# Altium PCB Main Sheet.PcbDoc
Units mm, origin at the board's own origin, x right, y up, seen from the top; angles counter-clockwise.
Board outline 34.5 x 33.5 mm, 2 copper layers (Top Layer, Bottom Layer); 20 components, 21 nets, 76 pads, 59 vias.
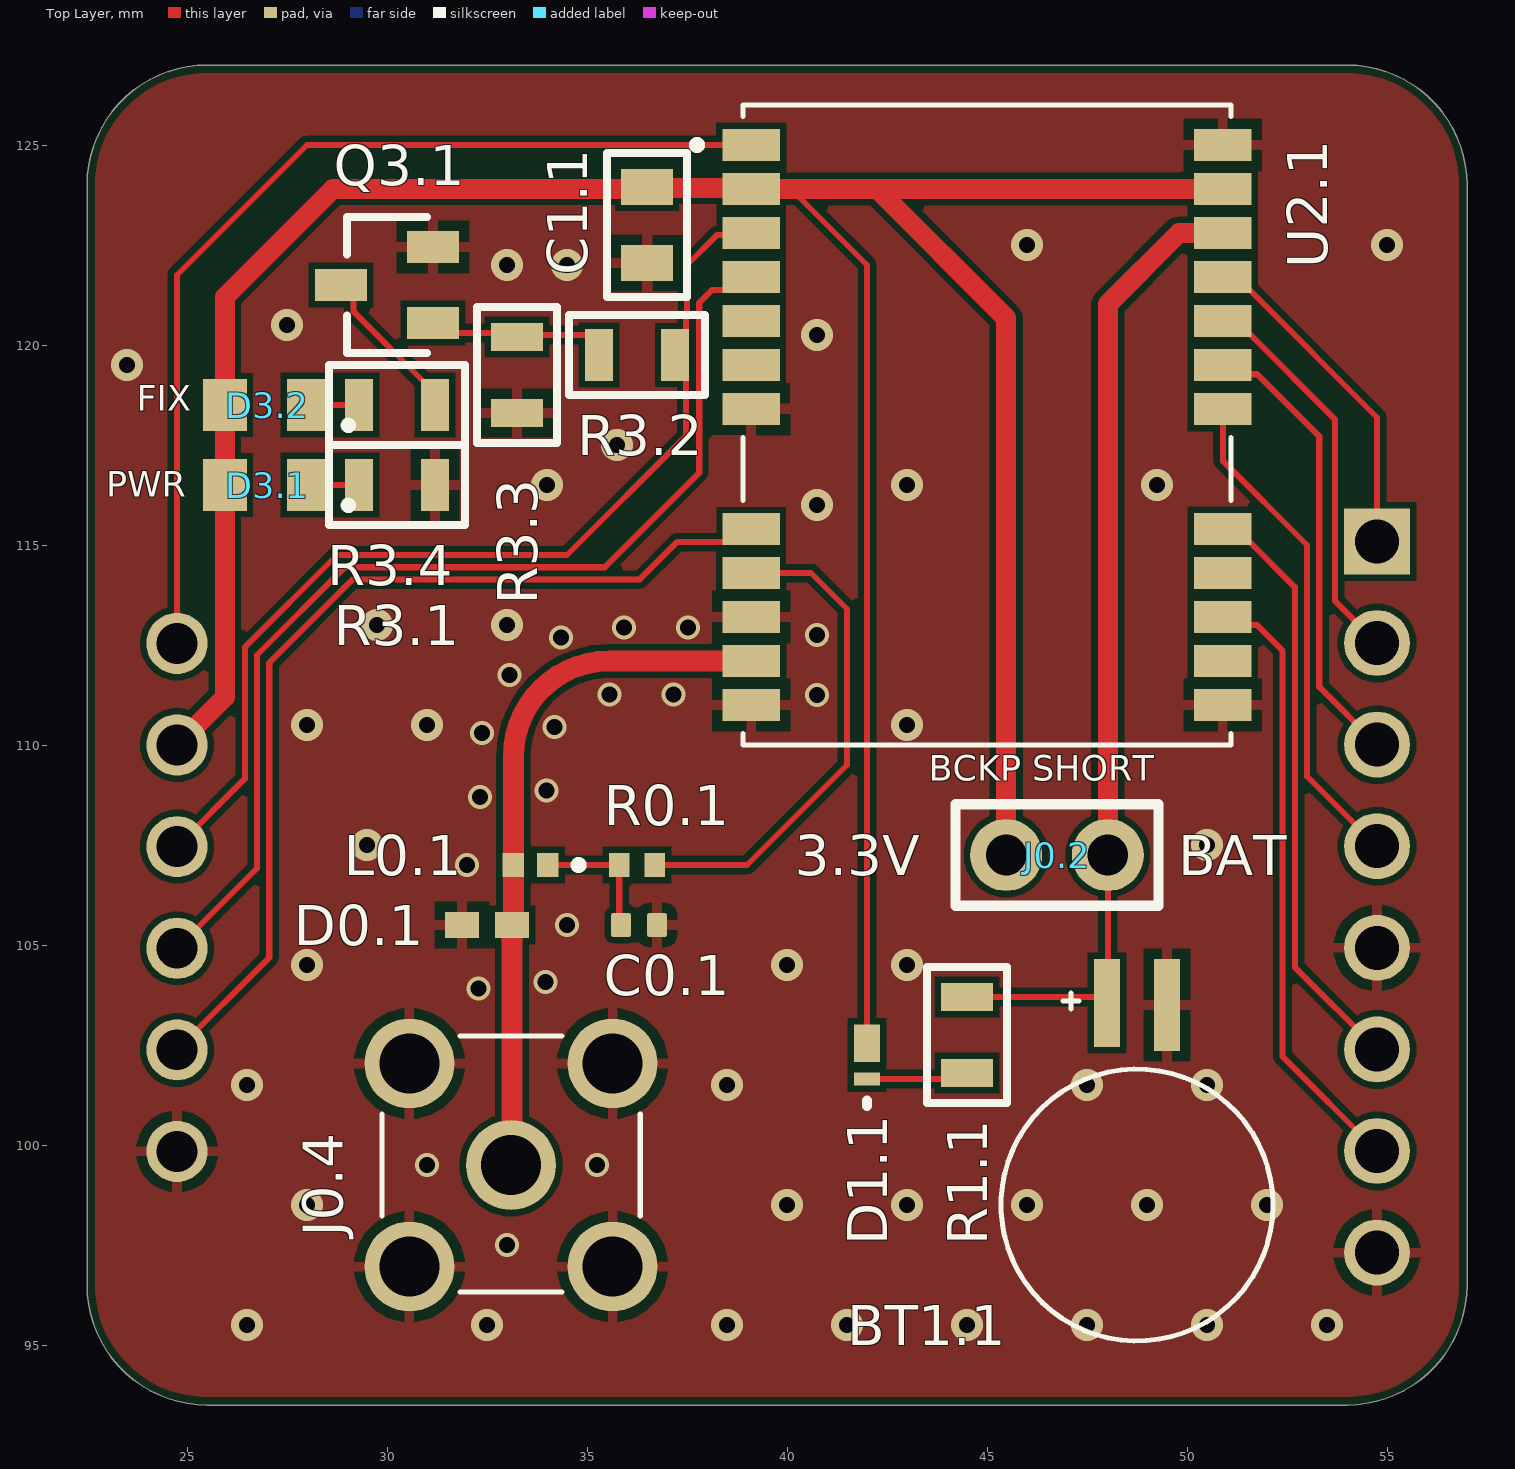
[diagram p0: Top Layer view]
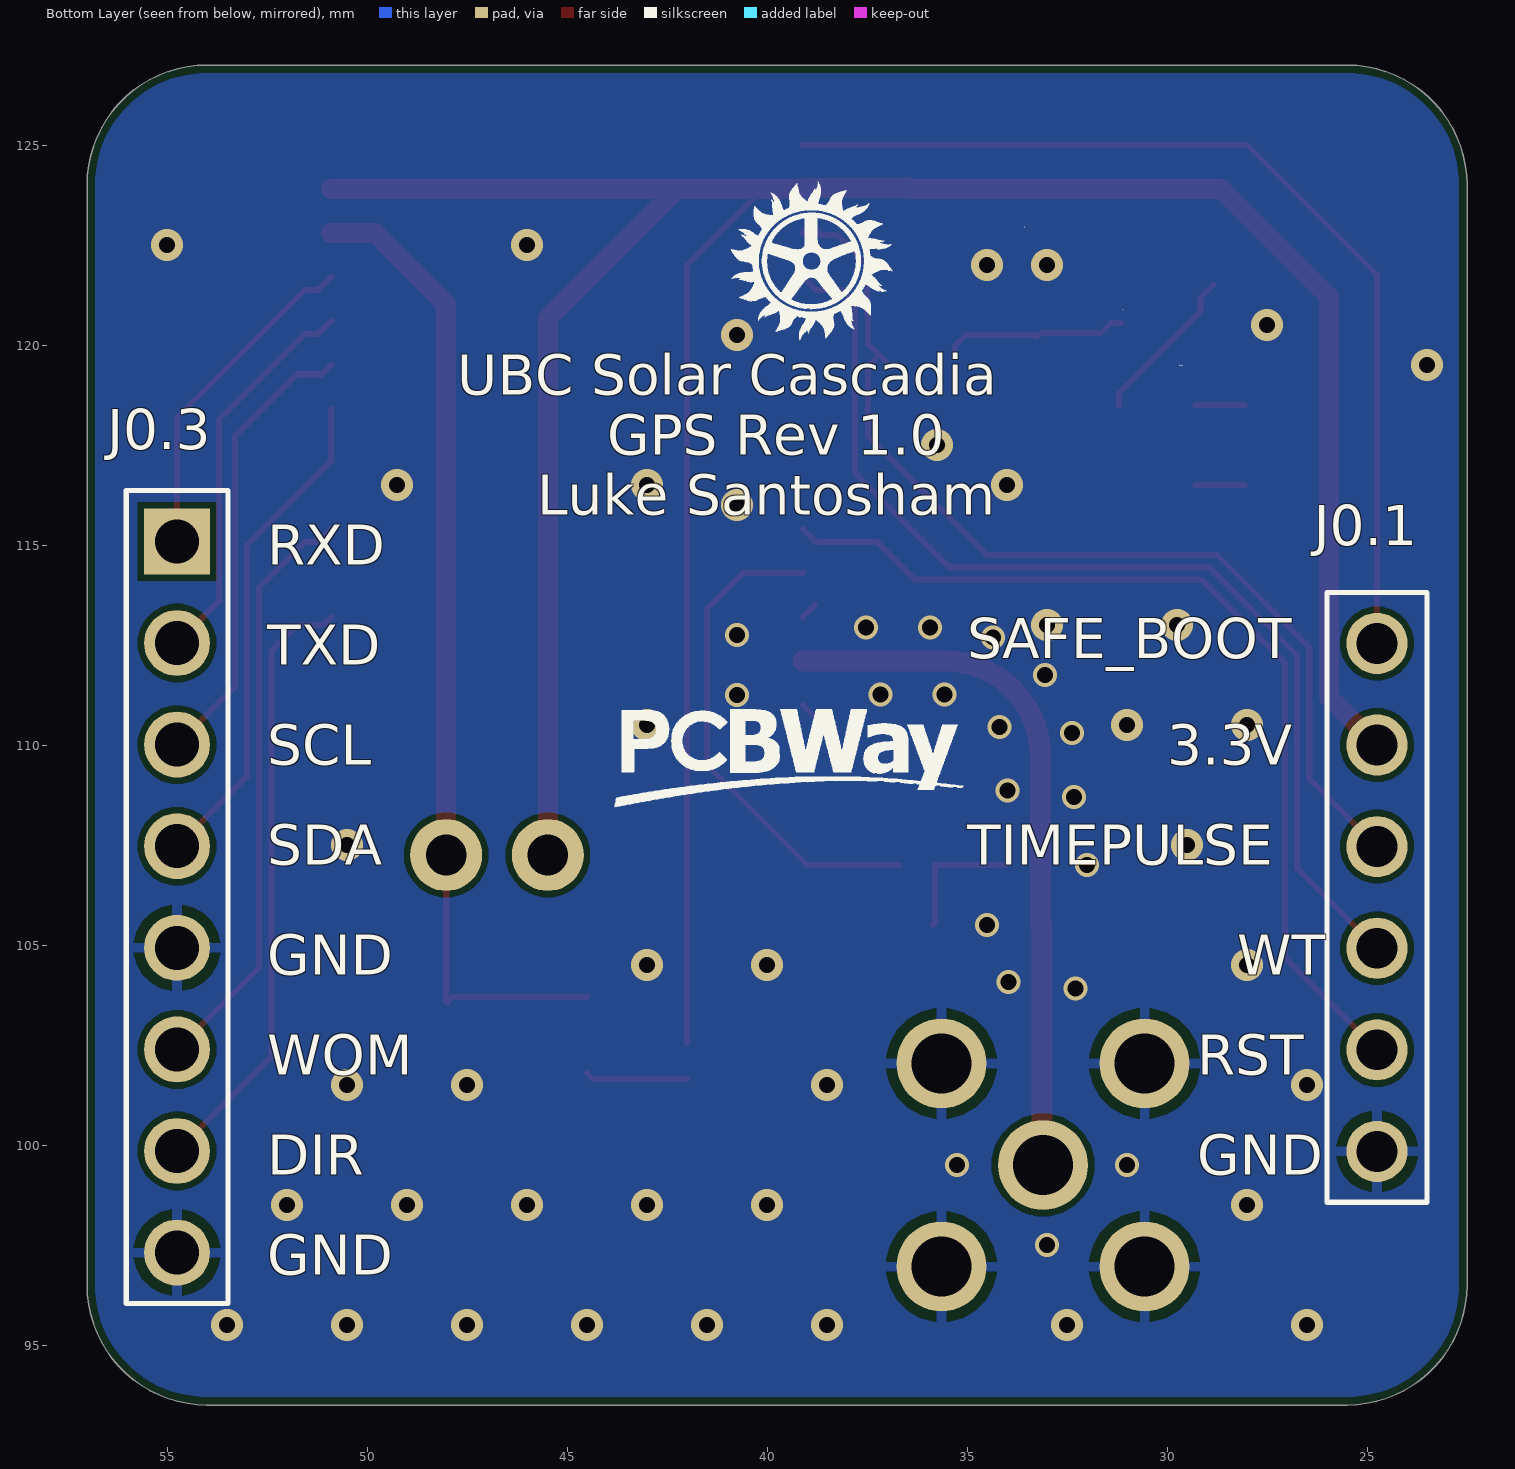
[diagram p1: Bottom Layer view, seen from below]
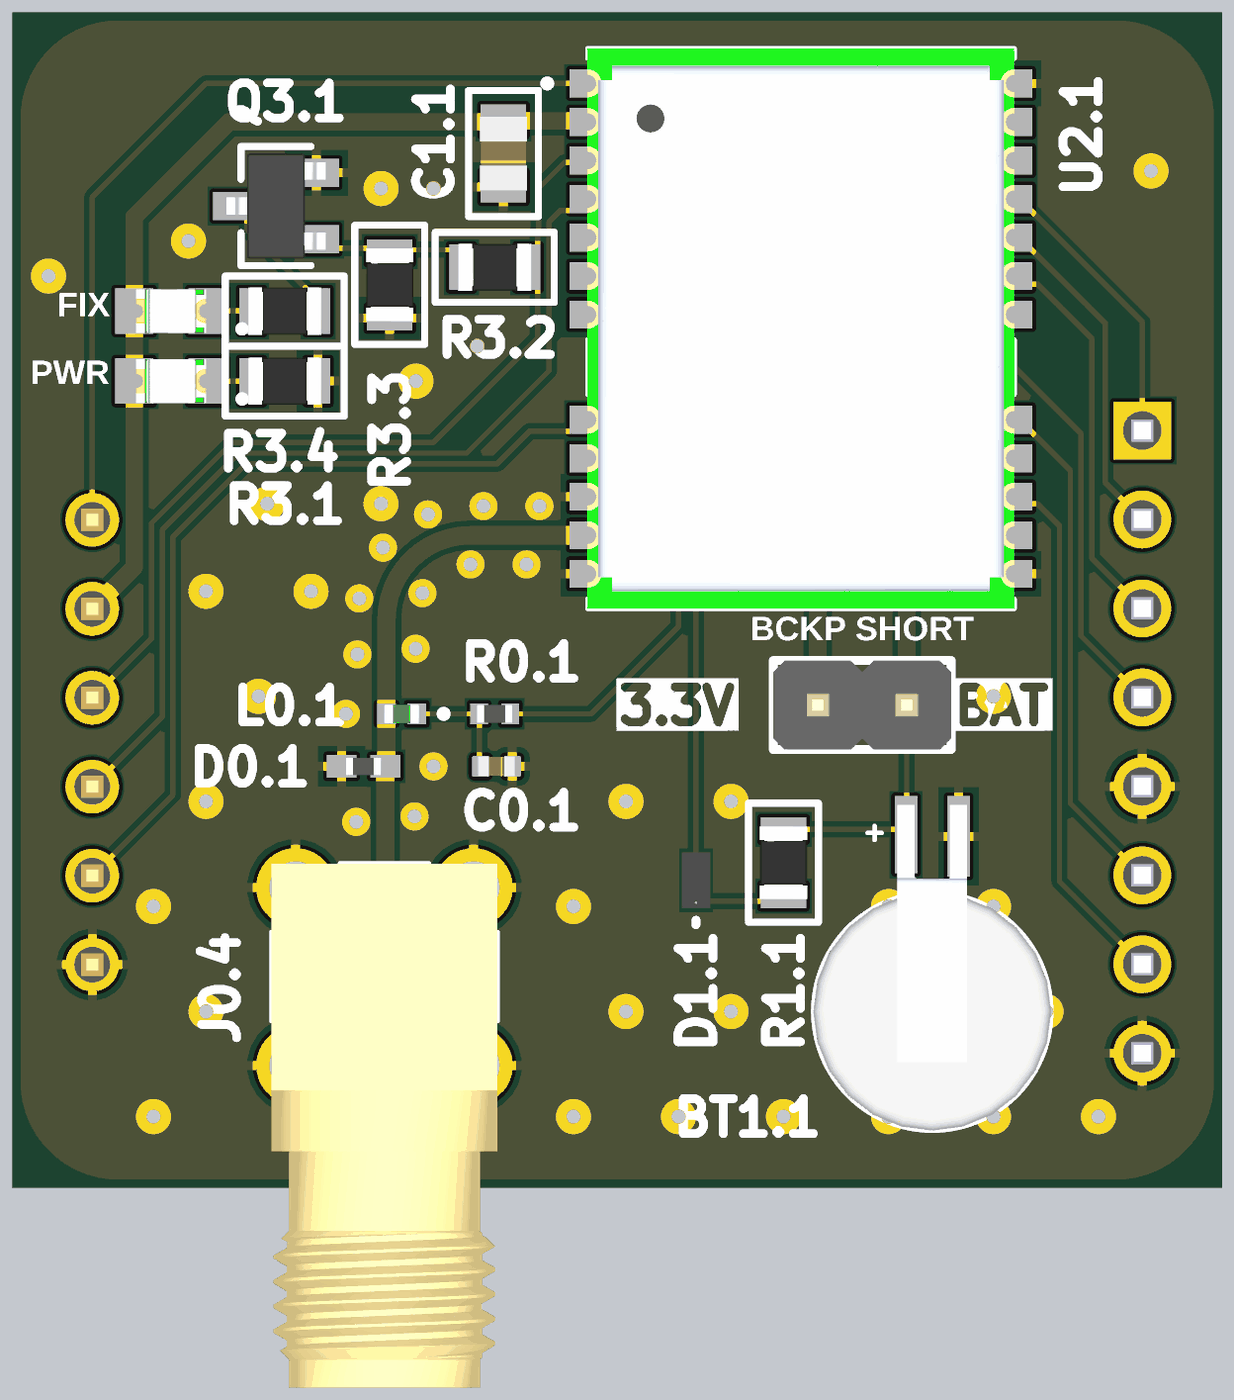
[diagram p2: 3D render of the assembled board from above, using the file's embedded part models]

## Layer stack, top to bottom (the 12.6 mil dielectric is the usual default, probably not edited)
Top Solder: solder mask 0.0102, Solder Resist, Dk 3.5
Top Layer: signal copper 0.0356
Dielectric 1: dielectric 0.32, FR-4, Dk 4.8
Bottom Layer: signal copper 0.0356
Bottom Solder: solder mask 0.0102, Solder Resist, Dk 3.5

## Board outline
25.5,93.5 cw(c25.5,96.5) 22.5,96.5 22.5,124 cw(c25.5,124) 25.5,127 54,127 cw(c54,124) 57,124 57,96.5 cw(c54,96.5) 54,93.5

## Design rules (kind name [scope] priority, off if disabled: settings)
BoardOutlineClearance [All] p1: gap=0.2 ignorepadtopadclearanceinfootprint=FALSE
Clearance [All] p1: gap=0.152 ignorepadtopadclearanceinfootprint=FALSE
HoleSize [All] p1: absolutevalues=TRUE maxlimit=100 minlimit=0.4 maxpercent=80.000 minpercent=20.000
MinimumSolderMaskSliver MinimumSolderMaskSliver_1 [InComponent('U2.1')] p1: minsoldermaskwidth=0
MinimumSolderMaskSliver [All] p2: minsoldermaskwidth=0.102
PolygonConnect PolygonConnect_1 [All vs isVia] p1: connectstyle=Direct reliefconductorwidth=0.254 reliefentries=4 polygonreliefangle="90 Angle" airgapwidth=0.254
PolygonConnect [All] p2: connectstyle=Relief reliefconductorwidth=0.254 reliefentries=4 polygonreliefangle="90 Angle" airgapwidth=0.254
RoutingVias [All] p1: holewidth=0.4 width=0.8 viastyle="Through Hole" minholewidth=0.4 minwidth=0.6 maxholewidth=100 maxwidth=100
SilkToSilkClearance [All] p1: silktosilkclearance=0
SilkToSolderMaskClearance [IsPad] p1: minsilkscreentomaskgap=0 clearancetoexposedcopper=TRUE
SolderMaskExpansion [All] p1: expansion=0.102 istentingtop=FALSE
SupplyNets "Schematic Supply Nets_2" [InNet('3.3V')] p1: voltage=0.000
SupplyNets "Schematic Supply Nets_1" [InNet('GND')] p2: voltage=0.000
SupplyNets "Schematic Supply Nets" [InNet('3V Coin')] p3: voltage=0.000
Width [All] p1: maxlimit=2.54 minlimit=0.152 preferedwidth=0.152
26 further rules are at their usual default settings.

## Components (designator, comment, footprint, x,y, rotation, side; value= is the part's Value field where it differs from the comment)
BT1.1 "3V" BAT_MS621FE-FL11E 48.75,98.5 r90 top
C0.1 "0402B104K160CT" CAPC1005X55N 36.3,105.5 r180 top value=100nF
C1.1 "1uF" C0805 36.5,123 r90 top
D0.1 "PESD0402-140" DIO_PESD0402-140 32.5,105.5 r0 top
D1.1 "VSKY20301608-G4-08" VSKY20301608-G4-08-Footprint-1 42,102.25 r90 top
D3.1 "GREEN" WL-SMCW_0805_150080xx75000 27,116.5 r180 top
D3.2 "GREEN" WL-SMCW_0805_150080xx75000 27,118.5 r180 top
J0.1 "0.1\" Header 6pos Male" "0.1\" Header 6pos Male-Footprint-1" 24.75,106.19 r90 bottom locked
J0.2 "0.1\" Header 2pos" "0.1%22 Header 2pos" 46.75,107.25 r180 top
J0.3 "0.1\" Header 8pos Male" "0.1\" Header 8pos Male-Footprint-1" 54.75,115.09 r270 bottom locked
J0.4 "RF2-03E-T-00-50-G" HUBER+SUHNER_85201239 33.1,99.5 r0 top
L0.1 "LQG15HS27NJ02D" INDC1005X55N 33.59,107 r0 top value=27nH
Q3.1 "DMN3023L-7" SOT-23-3 30,121.5 r90 top
R0.1 "RCS040210R0FKED" RESC1005X40N 36.25,107 r0 top value=10
R1.1 "620" "0805 General Resistor Footprint-Footprint-1" 44.5,102.75 r270 top
R3.1 "1k" "0805 General Resistor Footprint-Footprint-1" 30.25,116.5 r180 top
R3.2 "1k" "0805 General Resistor Footprint-Footprint-1" 36.25,119.75 r0 top
R3.3 "10k" "0805 General Resistor Footprint-Footprint-1" 33.25,119.25 r90 top
R3.4 "1k" "0805 General Resistor Footprint-Footprint-1" 30.25,118.5 r180 top
U2.1 "NEO-M9V-20B" XCVR_NEO-M9V-20B 45,118 r0 top

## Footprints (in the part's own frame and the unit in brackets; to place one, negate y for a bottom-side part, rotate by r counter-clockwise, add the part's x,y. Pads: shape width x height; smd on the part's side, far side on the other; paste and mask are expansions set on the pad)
"0.1\" Header 6pos Male-Footprint-1" [mm]
  round 1.53 hole 1.02: 1(-6.35,0) 2(-3.81,0) 3(-1.27,0) 4(1.27,0) 5(3.81,0) 6(6.35,0)
  silkscreen extent -7.62,-1.25 7.62,1.25, body extent -7.62,-1.25 7.62,1.25, height 8.5
"0.1\" Header 8pos Male-Footprint-1" [mm]
  rect 1.65x1.65 / inner round 1.65 / far side rect 1.65x1.65 hole 1.1: 1(0,0)
  round 1.65 hole 1.1: 2(2.54,0) 3(5.08,0) 4(7.62,0) 5(10.16,0) 6(12.7,0) 7(15.24,0) 8(17.78,0)
  silkscreen extent -1.27,-1.27 19.05,1.27, body extent -1.27,-1.27 19.05,1.27, height 8.39
"0.1%22 Header 2pos" [mm]
  round 1.8 hole 1.02: 1(-1.27,0) 2(1.27,0)
  silkscreen extent -2.54,-1.27 2.54,1.27, body extent -2.54,-1.27 2.54,1.27, height 8.38
"0805 General Resistor Footprint-Footprint-1" [mm]
  rect 0.7x1.3 smd: 1(-0.95,0) 2(0.95,0)
  silkscreen extent -1.7,-1 1.7,1, body extent -1.05,-0.67 1.05,0.68, height 0.6
BAT_MS621FE-FL11E [mm]
  rect 2.3x0.65 smd: NEG(5,-0.75)
  rect 2.2x0.65 smd: POS(5.05,0.75)
  silkscreen extent -3.4,-3.4 5.3,3.4, body extent -3.4,-3.4 5.9,3.4, height 2.8
C0805 [mm]
  rect 0.9x1.3 smd: 1(-0.95,0) 2(0.95,0)
  silkscreen extent -1.8,-1 1.8,1, body extent -1.05,-0.67 1.05,0.67, height 0.94
CAPC1005X55N [mm]
  rrect25% 0.5x0.6 smd: 1(-0.45,0) 2(0.45,0)
  body extent -0.52,-0.28 0.52,0.28, height 0.57
DIO_PESD0402-140 [mm]
  rect 0.85x0.65 smd paste+0 mask+0.102: 1(-0.625,0) 2(0.625,0)
  body extent -0.5,-0.25 0.5,0.25, height 0.43
HUBER+SUHNER_85201239 [mm]
  round 2.25 hole 1.5: 1(0,0) G1(-2.54,2.54) G2(2.54,2.54) G3(-2.54,-2.54) G4(2.54,-2.54)
  silkscreen extent -3.23,-3.17 3.23,3.23, body extent -3.23,-11.74 3.23,3.22, height 9.75
INDC1005X55N [mm]
  rect 0.54x0.6 smd: 1(-0.432,0) 2(0.432,0)
  silkscreen extent 1.1,-0.1 1.3,0.1, body extent -0.5,-0.28 0.5,0.27, height 0.51
RESC1005X40N [mm]
  rect 0.51x0.6 smd paste+0 mask+0.102: 1(-0.445,0) 2(0.445,0)
  body extent -0.5,-0.25 0.5,0.25, height 0.4
SOT-23-3 [mm]
  rect 0.8x1.3 smd: 1(-0.95,-1.15) 2(0.95,-1.15) 3(0,1.15)
  silkscreen extent -1.7,-1 1.7,1, body extent -1.5,-1.42 1.5,1.42, height 1.2
VSKY20301608-G4-08-Footprint-1 [mil]
  rect 13x26 smd paste+0 mask+0: 1(-23.5,0)
  rect 37x26 smd paste+0 mask+0: 2(11.5,0)
  silkscreen extent -50,0 -45,0, body extent -31,-16 31,16, height 12
WL-SMCW_0805_150080xx75000 [mm] "SMD Mono-color Chip LED, body 2.0x1.25mm"
  rect 1.1x1.3 smd: 1(-1.05,0) 2(1.05,0)
  silkscreen extent -2.1,0.44 -1.97,0.57, body extent -1,-0.63 1,0.62, height 0.7
XCVR_NEO-M9V-20B [mm]
  rect 1.44x0.8 smd: 1(-5.895,7) 2(-5.895,5.9) 3(-5.895,4.8) 4(-5.895,3.7) 5(-5.895,2.6) 6(-5.895,1.5) 7(-5.895,0.4) 8(-5.895,-2.6) 9(-5.895,-3.7) 10(-5.895,-4.8) 11(-5.895,-5.9) 12(-5.895,-7) 13(5.895,-7) 14(5.895,-5.9) 15(5.895,-4.8) 16(5.895,-3.7) 17(5.895,-2.6) 18(5.895,0.4) 19(5.895,1.5) 20(5.895,2.6) 21(5.895,3.7) 22(5.895,4.8) 23(5.895,5.9) 24(5.895,7)
  silkscreen extent -7.35,-8 6.1,8, body extent -6.1,-8 6.1,8, height 2.6

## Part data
BT1.1: library part CMP-104-000009-1, "Coin, 6.8mm 3 V Lithium Battery Rechargeable (Secondary) 5.5mAh / MS621FE-FL11E", Package="QFP-128 Seiko"
C0.1: library part CMP-156-000012-2, Package=None
C1.1: library part CMP-001-00083-2, "Replace name and description with the component intended"
D0.1: library part CMP-090-000018-1, "40V Clamp - Ipp Tvs Diode Surface Mount 0402", Package="0402 Littelfuse Inc."
D1.1: library part CMP-090-000019-2, "Rectifier Diode, Schottky, 1 Phase, 1 Element, 2A, 30V V(RRM), Silicon"
D3.1 D3.2: library part CMP-00065-4, "WURTH ELEKTRONIK - 150080GS75000 - LED, Green, SMD, 0805, 30 mA, 3.2 V, 520 nm", Case Code (Imperial)=0805, Case Code (Metric)=2012, Color=Green, Forward Current=100mA, Forward Voltage=3.2V, Max Junction Temperature (Tj)=95°C, Max Operating Temperature=85°C, Max Reverse Voltage (DC)=5V, Min Operating Temperature=-40°C, Power Dissipation=105mW, Test Current=20mA
J0.1: library part CMP-082-000075-5, Package=None
J0.2: library part CMP-023-0016-3
J0.3: library part CMP-082-000068-3, "PEC08SAAN --- Board Connector, 8 Contact(s), 1 Row(s), Male, Straight, 0.1 inch Pitch, Solder Terminal"
J0.4: library part CMP-082-000067-5, "SMA Connector Jack, Female Socket 50 Ohms Through Hole, Right Angle Solder", Package=None
L0.1: library part CMP-183-000003-3, "Inductor with Inductance: 27nH Tol. +/-5%, Package: 0402 _1005_", Package="1005 Murata"
Q3.1: library part CMP-039-0003-6, "N-Channel 30V 6.2A (Ta) 900mW (Ta) Surface Mount SOT-23", Supplier 1 Part Number=DMN3023L-7DICT-ND
R0.1: library part CMP-092-000055-2, "10 Ohms Â±1% 0.333W, 1/3W Chip Resistor 0402 (1005 Metric) Automotive AEC-Q200, Pulse Withstanding Thick Film", Package="1005 Panasonic Electronic Components"
R1.1 R3.1 R3.2 R3.3 R3.4: library part CMP-009-00226-2, "0805 resisitor"
U2.1: library part CMP-223-000000-1, "NEO-M9V RF Receiver BeiDou, Galileo, GLONASS, GNSS, GPS 1.561GHz -160dBm Not Included", Package=None

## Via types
v1: diameter 0.8, hole 0.4, Top Layer to Bottom Layer, 40 vias
v2: diameter 0.6, hole 0.4, Top Layer to Bottom Layer, 19 vias

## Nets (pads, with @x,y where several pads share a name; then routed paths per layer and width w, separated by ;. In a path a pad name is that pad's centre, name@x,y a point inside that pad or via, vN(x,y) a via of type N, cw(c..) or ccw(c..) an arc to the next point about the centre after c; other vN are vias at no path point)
3.3V: C1.1.2 D1.1.2 D3.1.2 D3.2.2 J0.1.5 J0.2.2 U2.1.2 U2.1.23 | length 77.7
  Top Layer w0.152: 40.25,123.75 42,122 D1.1.2
  Top Layer w0.5: J0.1.5 25.95,111.2 25.95,113.754 D3.1.2 D3.2.2 25.95,121.2 28.65,123.9 36.45,123.9 C1.1.2 36.525,123.925 39.08,123.925 U2.1.2 40.25,123.9 42.25,123.9 ; J0.2.2 45.48,120.67 42.25,123.9 ; U2.1.23 42.25,123.9
"3V Coin": BT1.1.POS J0.2.1 R1.1.1 U2.1.22 | length 24.7
  Top Layer w0.152: R1.1.1 47.85,103.7 BT1.1.POS 48.02,103.57 J0.2.1
  Top Layer w0.5: J0.2.1 48.02,121.02 49.8,122.8 U2.1.22
DIR: J0.3.7 U2.1.15 | length 15.3
  Top Layer w0.152: U2.1.15 51.099,112.996 51.754,112.996 52.383,112.367 52.383,102.217 J0.3.7
Fix_LED: J0.1.4 R3.2.2 U2.1.3 | length 25.9
  Top Layer w0.152: J0.1.4 26.445,109.155 26.445,112.445 28.75,114.75 34.5,114.75 37.474,117.724 37.474,119.476 R3.2.2 ; R3.2.2@36.95,119.5 R3.2.2 ; U2.1.3 38.905,123 38.651,122.746 38.246,122.746 37.5,122 37.5,120.75 37.474,120.724 37.474,120.024 R3.2.2
GND: BT1.1.NEG C0.1.1 C1.1.1 D0.1.1 J0.1.1 J0.3.5 J0.3.8 J0.4.G1 J0.4.G2 J0.4.G3 J0.4.G4 Q3.1.2 R3.1.1 R3.3.1 U2.1.7 U2.1.10 U2.1.12 U2.1.13 U2.1.24 | length 0.8
  Top Layer w0.152: U2.1.10@38.805,113.5 U2.1.10 ; U2.1.12@38.855,110.75 U2.1.12
  other v1: 26.5,95.5 32.5,95.5 38.5,95.5 41.5,95.5 44.5,95.5 47.5,95.5 50.5,95.5 53.5,95.5 28,98.5 40,98.5 43,98.5 46,98.5 49,98.5 52,98.5 26.5,101.5 38.5,101.5 47.5,101.5 50.5,101.5 28,104.5 40,104.5 43,104.5 29.5,107.5 50.5,107.5 28,110.5 31,110.5 43,110.5 29.75,113 33,113 40.75,116 34,116.5 43,116.5 49.25,116.5 35.75,117.5 23.5,119.5 40.75,120.25 27.5,120.5 33,122 34.5,122 46,122.5 55,122.5
  other v2: 33,97.5 31,99.5 35.25,99.5 32.293,103.916 33.957,104.071 34.5,105.5 32,107 32.326,108.697 33.99,108.859 32.38,110.296 34.185,110.447 40.75,111.25 35.558,111.268 37.158,111.268 33.056,111.746 34.345,112.694 40.75,112.75 35.927,112.932 37.527,112.932
NetC0.1_2: C0.1.2 L0.1.2 R0.1.1 | length 3.3
  Top Layer w0.152: L0.1.2 34.671,107 R0.1.1 35.805,105.545 C0.1.2
NetD1.1_1: D1.1.1 R1.1.2 | length 2.6
  Top Layer w0.152: D1.1.1 44.353,101.653 R1.1.2
NetD3.1_1: D3.1.1 R3.1.2 | length 1.3
  Top Layer w0.152: D3.1.1 R3.1.2
NetD3.2_1: D3.2.1 R3.4.2 | length 1.3
  Top Layer w0.152: D3.2.1 R3.4.2
NetQ3.1_1: Q3.1.1 R3.2.1 R3.3.2 | length 4.7
  Top Layer w0.152: Q3.1.1 31.4,120.55 31.65,120.3 33.15,120.3 R3.3.2 33.3,120.25 35.026,120.25 35.3,119.976 R3.2.1
NetQ3.1_3: Q3.1.3 R3.4.1 | length 4
  Top Layer w0.152: Q3.1.3 29.166,121.184 29.166,120.834 31,119 31.2,118.8 R3.4.1
Reset: J0.1.2 U2.1.8 | length 24.1
  Top Layer w0.152: J0.1.2 27.055,104.685 27.055,112.055 29.14,114.14 36.321,114.14 37.257,115.076 38.781,115.076 U2.1.8
RF_IN: D0.1.2 J0.4.1 L0.1.1 U2.1.11 | length 17.6
  Top Layer w0.525: J0.4.1 33.125,99.525 D0.1.2 33.158,105.5 L0.1.1 33.158,109.71 cw(c35.548,109.71) 35.548,112.1 U2.1.11
RXD: J0.3.1 U2.1.21 | length 8.4
  Top Layer w0.152: U2.1.21 51.219,121.376 51.562,121.376 54.75,118.188 J0.3.1
Safeboot: J0.1.6 U2.1.1 | length 24.9
  Top Layer w0.152: J0.1.6 24.75,121.75 28,125 U2.1.1
SCL: J0.3.3 U2.1.19 | length 11.5
  Top Layer w0.152: U2.1.19 51.126,119.269 51.754,119.269 53.305,117.718 53.305,111.455 J0.3.3
SDA: J0.3.4 U2.1.18 | length 12.5
  Top Layer w0.152: U2.1.18 50.895,117.105 53,115 53,109.22 J0.3.4
TXD: J0.3.2 U2.1.20 | length 9.8
  Top Layer w0.152: U2.1.20 51.219,120.276 51.562,120.276 53.696,118.142 53.696,113.604 J0.3.2
VCC_RF: R0.1.2 U2.1.9 | length 12.5
  Top Layer w0.152: R0.1.2 39,107 41.5,109.5 41.5,113.4 40.6,114.3 U2.1.9
Wake_On_Motion: J0.3.6 U2.1.17 | length 14.8
  Top Layer w0.152: U2.1.17 51.219,115.076 51.562,115.076 52.695,113.943 52.695,104.445 J0.3.6
Wheel_Tick: J0.1.3 U2.1.4 | length 26.9
  Top Layer w0.152: J0.1.3 26.75,106.92 26.75,112.25 28.945,114.445 35.445,114.445 37.805,116.805 37.805,121.055 38.126,121.376 38.781,121.376 U2.1.4
pads on no net: U2.1.5 U2.1.6 U2.1.14 U2.1.16

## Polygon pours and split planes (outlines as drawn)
GND on Bottom Layer "Ground" (solid, pour order 11): 22.5,127 57,127 57,93.5 22.5,93.5
GND on Top Layer "Ground" (solid, pour order 5): 22.5,127 57,127 57,93.5 22.5,93.5

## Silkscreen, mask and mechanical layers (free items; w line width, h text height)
Top Overlay:
  text "FIX" at 23.747,118.148 h1.1
  text "PWR" at 22.986,115.997 h1.1
  text "BCKP SHORT" at 43.549,108.898 h1.1
  text "3.3V" at 40.197,106.75 h1
  text "BAT" at 49.78,106.75 h1
Bottom Overlay:
  drawing of 14 lines, arcs and shapes, not listed
  text "UBC Solar Cascadia" at 47.746,118.754 h1
  text "GPS Rev 1.0" at 43.996,117.254 h1
  text "Luke Santosham" at 45.746,115.754 h1
  text "RXD" at 52.496,114.504 h1
  text "SAFE_BOOT" at 34.996,112.171 h1
  text "TXD" at 52.496,112.004 h1
  text "3.3V" at 29.996,109.504 h1
  text "SCL" at 52.496,109.504 h1
  text "TIMEPULSE" at 34.996,107.004 h1
  text "SDA" at 52.496,107.004 h1
  text "WT" at 28.246,104.254 h1
  text "GND" at 52.496,104.254 h1
  text "RST" at 29.246,101.754 h1
  text "WOM" at 52.496,101.754 h1
  text "GND" at 29.246,99.254 h1
  text "DIR" at 52.496,99.254 h1
  text "GND" at 52.496,96.754 h1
